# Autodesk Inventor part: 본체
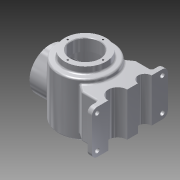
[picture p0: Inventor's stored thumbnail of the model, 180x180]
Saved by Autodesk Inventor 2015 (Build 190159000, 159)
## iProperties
Created: 2018-08
Part Number: 본체
Material: 알루미늄 6061
Document SubType Name: Modeling
Designer: line
Density: 2.7 g/cm^3
Appearance: 알루미늄 - 평지
Mass: 1879.13 g
Surface Area: 1087.48 cm^2
Volume: 695.975 cm^3
Author: line
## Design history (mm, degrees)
sketch "스케치2"
  geometry: L1 (0, 54)-(50, 54); L2 (0, 54)-(0, -54); L3 (0, 54)-(50, 54); L4 (0, 54)-(0, -54); L5 (50, -42.671)-(50, 54); A1 r 116 centre (0, 62) between (0, -54) and (50, -42.671); 1 further point
  constraints: 10 end point, 2 point on circle, 1 centre point, 1 collinear, 1 horizontal
  dimensions: "d14" = 108 vertical distance of L2.end L1.end; "d16" = 50 distance of L1.start L1.end; "d17" = 116 radius of A1; "d18" = 108 distance of L1.start L2.end; "d19" = 50 horizontal distance of L5.start A1.centre; "d20" = 62 distance of point (0, 0) A1.centre; "d21" = 8 vertical distance of L1.end A1.centre
revolve "회전1" sketch "스케치2" stored, may be unused: angle "d22" = 90 deg
sketch "스케치3"
  geometry: C1 r 38 at (0, 0); 1 further point
  constraints: 1 centre point, 1 coincident
  dimensions: "d23" = 76 diameter of C1
extrude "돌출1" join sketch "스케치3" distance "d24" = 12; taper "d25" = 0 deg
sketch "스케치4"
  geometry: C1 r 27 at (0, 0); 1 further point
  constraints: 1 centre point, 1 coincident
  dimensions: "d26" = 54 diameter of C1
extrude "돌출2" cut sketch "스케치4" distance "d27" = 22; taper "d28" = 0 deg
sketch "스케치5" dims "d29" = 65
  geometry: 3 further points
  constraints: 2 vertical alignment, 1 coincident, 2 other
hole "구멍1" sketch "스케치5" at (0, 32.5) diameter "d30" = 3.242; stored, may be unused: countersink angle "d34" = 90 deg, drill point angle "d36" = 118 deg; dims "d31" = 8, "d32" = 4, "d33" = 2, "d35" = 10
sketch "스케치6"
  geometry: L1 (0, 66)-(0, -63.544); L2 (0, 44)-(40, 44); L3 (40, 44)-(40, -36.163); L4 (0, 44)-(40, 44); L5 (40, -36.163)-(40, 44); L6 (-27, 44)-(27, 44) reference; L7 (0, 44)-(0, -44); A1 r 106 centre (0, 62) between (0, -44) and (40, -36.163); 1 further point
  constraints: 12 end point, 2 perpendicular, 2 point on circle, 1 centre point, 1 collinear, 1 point on line, 1 vertical
  dimensions: "d41" = 40 distance of L2.start L2.end; "d42" = 106 radius of A1; "d43" = 80.16313 distance of L2.end L3.end; "d44" = 129.54354 distance of L1.start L1.end; "d45" = 18 distance of L2.start A1.centre; "d46" = 44 distance of L7.end point (0, 0); "d47" = 63.54354 distance of L1.end point (0, 0); "d48" = 40 horizontal distance of A1.centre L2.end
revolve "회전2" sketch "스케치6" stored, may be unused: angle "d49" = 90 deg
node "작업 평면1"
sketch "스케치7"
  geometry: L1 (-1.621, 66)-(1.621, 66) reference; L2 (0, 66)-(0, 4); C1 r 38 at (0, 4); 1 further point
  constraints: 2 end point, 1 centre point, 1 coincident, 1 midpoint, 1 vertical
  dimensions: "d51" = 62 distance of L2.start L2.end; "d52" = 76 diameter of C1
extrude "돌출3" join sketch "스케치7" stored distance "d53" = 22; taper "d54" = 0 deg
sketch "스케치8"
  geometry: C1 r 38 at (0, 0) reference; C2 r 27 at (0, 0); 1 further point
  constraints: 1 centre point, 1 coincident
  dimensions: "d55" = 54 diameter of C2
extrude "돌출4" cut sketch "스케치8" stored distance "d56" = 22; taper "d57" = 0 deg
sketch "스케치9" dims "d58" = 65
  geometry: C1 r 38 at (0, 0) reference; 3 further points
  constraints: 2 vertical alignment, 1 coincident, 2 other
hole "구멍2" sketch "스케치9" at (0, -32.5) diameter "d59" = 3.242; stored, may be unused: countersink angle "d63" = 90 deg, drill point angle "d65" = 118 deg; dims "d60" = 8, "d61" = 4, "d62" = 2, "d64" = 10
chamfer "모따기1" distance "d69" = 1; stored, may be unused: second distance "d70" = 2, angle "d71" = 45 deg
node "작업 평면2"
sketch "스케치11"
  geometry: L1 (0, 0)-(82, 0); L2 (82, 0)-(82, -70); L3 (82, -70)-(72, -70); L4 (72, -70)-(72, -50); L5 (72, -50)-(43.437, -50); L6 (43.437, -50)-(27.371, -38.751); L7 (82, 0)-(82, 70); L8 (82, 70)-(72, 70); L9 (72, 70)-(72, 50); L10 (72, 50)-(43.437, 50); L11 (43.437, 50)-(27.371, 38.751); C1 r 50 at (0, 0) reference; A1 r 47.442 centre (0, 0) between (27.371, -38.751) and (27.371, 38.751); 1 further point
  constraints: 22 end point, 6 perpendicular, 2 point on circle, 2 vertical, 1 centre point, 1 coincident, 1 horizontal
  dimensions: "d86" = 82 distance of L1.start L1.end; "d88" = 70 distance of L1.end L2.end; "d89" = 10 distance of L2.end L3.end; "d90" = 20 distance of L3.end L4.end; "d91" = 35 deg angle of L3 L6; "d92" = 70 distance of L1.end L7.end; "d93" = 10 distance of L7.end L8.end; "d94" = 20 distance of L8.end L9.end; "d95" = 35 deg angle of L11 L8; "d96" = 47.44242 radius of A1; "d97" = 16.0659 horizontal distance of L10.end L11.end; "d98" = 16.0659 horizontal distance of L5.end L6.end
extrude "돌출5" join sketch "스케치11" distance "d99" = 80; taper "d100" = 0 deg
sketch "스케치12"
  geometry: L1 (82, 70)-(82, -70) reference; L2 (82, 70)-(82, -70) reference; C1 r 17.5 at (82, -22.5); C2 r 12.5 at (82, 27.5); 4 further points
  constraints: 2 centre point, 2 coincident, 2 point on line, 2 vertical alignment, 1 midpoint
  dimensions: "d101" = 22.5 distance of point (82, 0) point (82, -22.5); "d102" = 27.5 distance of point (82, 27.5) point (82, 0); "d103" = 35 diameter of C1; "d104" = 25 diameter of C2
extrude "돌출6" cut sketch "스케치12" stored distance "d105" = 80; taper "d106" = 0 deg
fillet "모깎기1" dims "d107" = 3
fillet "모깎기2" dims "d108" = 10
fillet "모깎기3" dims "d109" = 3
sketch "스케치13"
  geometry: C1 r 4 at (10, -20); C2 r 4 at (70, -20); C3 r 4 at (10, 100); C4 r 4 at (70, 100); A1 r 10 centre (10, -20) between (0, -20) and (10, -30) reference; A2 r 10 centre (70, -20) between (70, -30) and (80, -20) reference; A3 r 10 centre (70, 100) between (80, 100) and (70, 110) reference; A4 r 10 centre (10, 100) between (10, 110) and (0, 100) reference; 1 further point
  constraints: 4 centre point, 4 coincident
  dimensions: "d110" = 8 diameter of C1; "d111" = 8 diameter of C2; "d112" = 8 diameter of C3; "d113" = 8 diameter of C4
extrude "돌출7" cut sketch "스케치13" distance "d114" = 20; taper "d115" = 0 deg
node "작업 평면3"
sketch "스케치14"
  geometry: C1 r 32.5 at (0, 0); 1 further point
  constraints: 1 centre point, 1 coincident, 1 other
  dimensions: "d116" = 65 diameter of C1
feature "엠보싱1" sketch "스케치14" dims "d14" = 108, "d16" = 50, "d17" = 116, "d18" = 108, "d19" = 50, "d20" = 62, "d21" = 8, "d117" = 0.5, "d118" = 0
node "솔리드1"
pattern_circular "원형 패턴1" dims angle "d38" = 360 deg
pattern_circular "원형 패턴2" dims angle "d67" = 360 deg
other parameters: "d4" = 116, "d13" = 116, "d50" = -65, "d85" = -8
